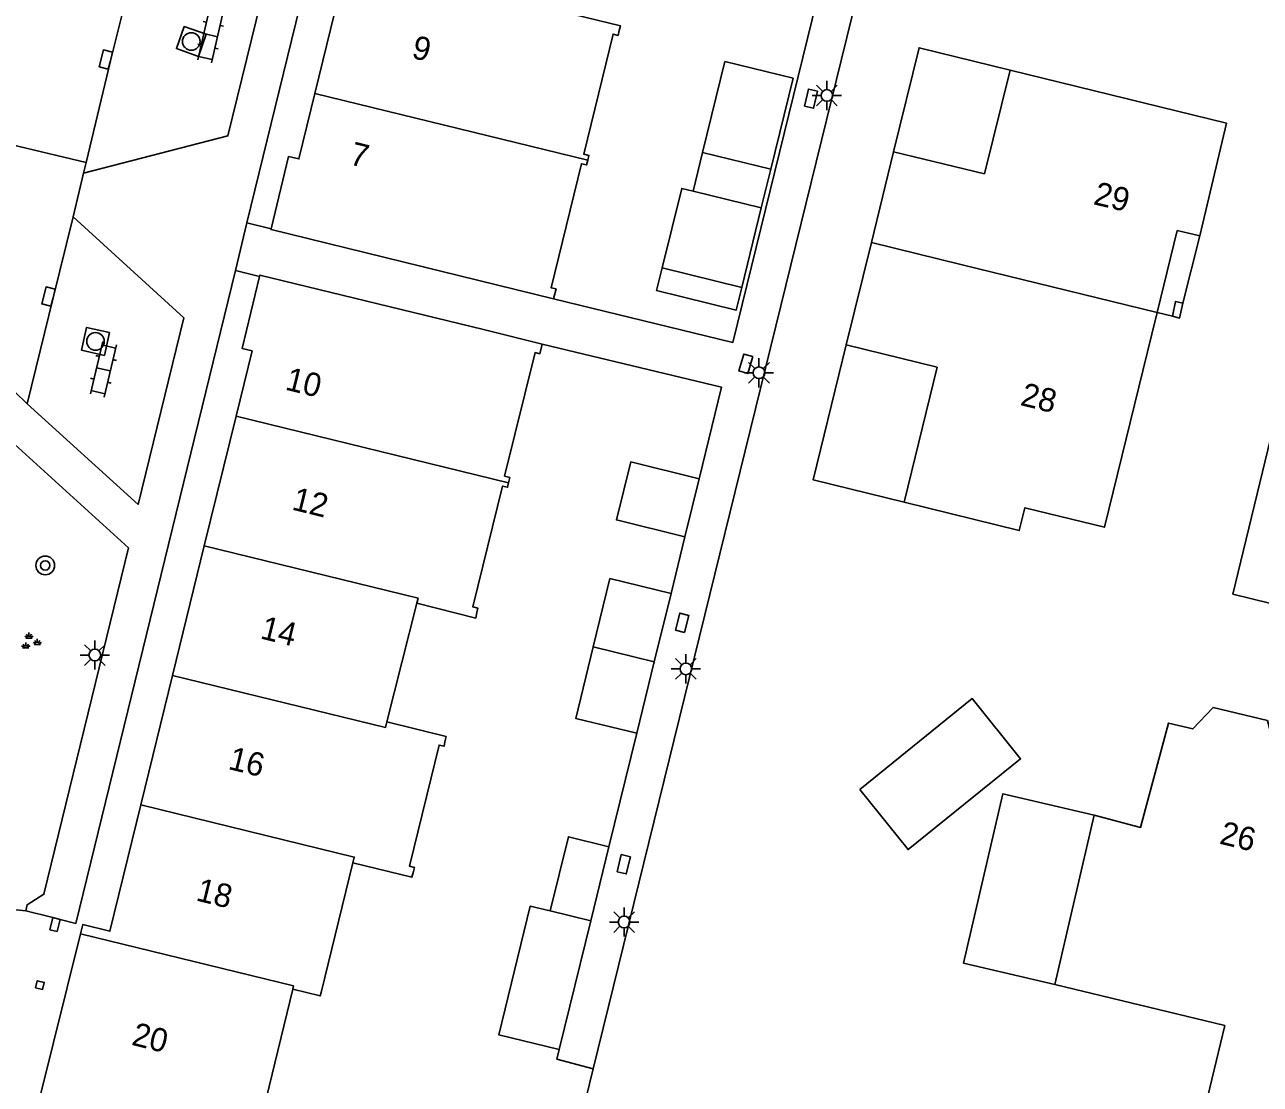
# Model space of a CAD drawing. Extents: x 125000 to 129004, y 397500 to 399008.
# Drawn here: x 126559.6 to 126612.3, y 398186.4 to 398231.7 of the extents above; entities that cross this region are included whole.
import ezdxf

# ---------------------------------------------------------------- set-up
doc = ezdxf.new("R2010")
doc.units = 0
for name, color, linetype in [('gg-afsc-hekwerk', 7, 'Continuous'), ('gg-afsc-muur', 7, 'Continuous'), ('gg-anno-huisnummerreeks BGT', 7, 'Continuous'), ('gg-bbg-bijgebouw', 7, 'Continuous'), ('gg-bbg-gedigitaliseerde bebouwing', 7, 'Continuous'), ('gg-bbg-gedigitaliseerde bijgebouw', 7, 'Continuous'), ('gg-bbg-hoofdgebouw', 7, 'Continuous'), ('gg-bbg-luifel en loopbrug', 7, 'Continuous'), ('gg-bbg-onder overbouw', 7, 'Continuous'), ('gg-bbg-pand overbouw', 7, 'Continuous'), ('gg-bbg-pilaar onder overbouw', 7, 'Continuous'), ('gg-bbg-pilaar pand', 7, 'Continuous'), ('gg-bbg-tussenscheiding', 7, 'Continuous'), ('gg-knt-verharding', 7, 'Continuous'), ('gg-knt-verharding nz', 7, 'Continuous'), ('gt-grn-groengrens', 7, 'Continuous'), ('gt-grn-weggrens', 7, 'Continuous'), ('gt-symb-boom', 7, 'Continuous'), ('gt-symb-groenvak', 7, 'Continuous'), ('gt-symb-klinker verharding', 7, 'Continuous'), ('gt-symb-kolk', 7, 'Continuous'), ('gt-symb-kolk center center', 7, 'Continuous'), ('gt-symb-lichtmast', 7, 'Continuous'), ('gt-symb-rioolschacht', 7, 'Continuous')]:
    doc.layers.add(name, color=color, linetype=linetype)

# ---------------------------------------------------------------- blocks, each defined once
blk = doc.blocks.new('gt0-LMAST')
at = {"layer": 'gt-symb-lichtmast'}
for p, q in [((-0.005, 0.246), (-0.005, 0.621)), ((-0.182, 0.173), (-0.447, 0.438)), ((0.172, 0.173), (0.437, 0.438)), ((-0.255, -0.004), (-0.63, -0.004)), ((-0.182, -0.181), (-0.447, -0.446)), ((-0.005, -0.254), (-0.005, -0.629)), ((0.437, -0.446), (0.172, -0.181)), ((0.245, -0.004), (0.62, -0.004))]:
    blk.add_line(p, q, dxfattribs=at)
blk.add_circle((-0.005, -0.004), 0.25, dxfattribs=at)
blk = doc.blocks.new('gt0-KOLKCC')
at = {"layer": 'gt-symb-kolk center center'}
blk.add_lwpolyline([(-0.375, 0.2), (0.375, 0.2), (0.375, -0.2), (-0.375, -0.2)], close=True, dxfattribs=at)
blk = doc.blocks.new('gt0-KOLK')
at = {"layer": 'gt-symb-kolk'}
blk.add_lwpolyline([(0, 0), (0.375, 0), (0.375, 0.4), (-0.375, 0.4), (-0.375, 0), (0, 0)], dxfattribs=at)
blk = doc.blocks.new('gt0-RS')
at = {"layer": 'gt-symb-rioolschacht'}
blk.add_lwpolyline([(-0.5, -0.5), (0.5, -0.5), (0.5, 0.5), (-0.5, 0.5)], close=True, dxfattribs=at)
blk.add_circle((0, 0), 0.375, dxfattribs=at)
blk = doc.blocks.new('gt0-KL1')
at = {"layer": 'gt-symb-klinker verharding'}
for p, q in [((-1.15, 0.3), (1.15, 0.3)), ((-1, -0.3), (-1, 0.3)), ((-0.5, 0.3), (-0.5, 0.45)), ((0, -0.3), (0, 0.3)), ((0.5, 0.3), (0.5, 0.45)), ((1, -0.3), (1, 0.3)), ((-1.15, -0.3), (1.15, -0.3)), ((-0.5, -0.45), (-0.5, -0.3)), ((0.5, -0.45), (0.5, -0.3))]:
    blk.add_line(p, q, dxfattribs=at)
blk = doc.blocks.new('gt0-GRVAK')
at = {"layer": 'gt-symb-groenvak'}
for p, q in [((-0.11, 0.189), (-0.228, 0.24)), ((-0.182, 0.153), (0.088, 0.153)), ((-0.091, 0.211), (-0.156, 0.322)), ((-0.047, 0.214), (-0.047, 0.393)), ((-0.004, 0.211), (0.061, 0.322)), ((0.015, 0.189), (0.133, 0.24)), ((0.262, -0.052), (0.197, 0.059)), ((0.305, -0.049), (0.305, 0.13)), ((0.349, -0.052), (0.414, 0.059)), ((-0.245, -0.228), (-0.363, -0.177)), ((-0.318, -0.264), (-0.047, -0.264)), ((-0.226, -0.206), (-0.291, -0.095)), ((-0.183, -0.203), (-0.183, -0.024)), ((-0.139, -0.206), (-0.074, -0.095)), ((-0.12, -0.228), (-0.002, -0.177)), ((0.243, -0.074), (0.125, -0.023)), ((0.17, -0.11), (0.441, -0.11)), ((0.368, -0.074), (0.486, -0.023))]:
    blk.add_line(p, q, dxfattribs=at)
blk = doc.blocks.new('gt0-BOOM')
at = {"layer": 'gt-symb-boom'}
for radius in [0.4, 0.2]:
    blk.add_circle((0, 0), radius, dxfattribs=at)

msp = doc.modelspace()

# ---------------------------------------------------------------- linework, layer by layer
at = {"layer": 'gg-afsc-hekwerk'}
for p, q in [((126598.275, 398245.797), (126583.84, 398187.058)), ((126583.84, 398187.058), (126583.293, 398184.831))]:
    msp.add_line(p, q, dxfattribs=at)
at = {"layer": 'gg-afsc-muur'}
msp.add_line((126561.064, 398193.438), (126560.753, 398193.513), dxfattribs=at)
for points in [[(126560.753, 398193.513), (126560.628, 398192.998), (126560.939, 398192.923), (126561.064, 398193.438)], [(126560.016, 398190.519), (126560.092, 398190.819), (126560.393, 398190.743), (126560.317, 398190.443), (126560.016, 398190.519)]]:
    msp.add_lwpolyline(points, dxfattribs=at)
at = {"layer": 'gg-bbg-bijgebouw'}
msp.add_lwpolyline([(126595.222, 398198.988), (126597.29, 398196.422), (126602.095, 398200.294), (126600.027, 398202.873), (126595.222, 398198.988)], dxfattribs=at)
at = {"layer": 'gg-bbg-gedigitaliseerde bebouwing'}
for p, q in [((126600.557, 398225.292), (126601.645, 398229.732)), ((126595.719, 398222.358), (126596.671, 398226.244)), ((126596.671, 398226.244), (126600.557, 398225.292)), ((126595.719, 398222.358), (126594.649, 398217.988)), ((126594.649, 398217.988), (126598.533, 398217.036)), ((126597.119, 398211.265), (126598.533, 398217.036))]:
    msp.add_line(p, q, dxfattribs=at)
at = {"layer": 'gg-bbg-gedigitaliseerde bijgebouw'}
for p, q in [((126588.509, 398226.212), (126591.423, 398225.497)), ((126591.017, 398223.843), (126588.103, 398224.558)), ((126590.182, 398220.444), (126591.017, 398223.843)), ((126586.783, 398221.278), (126590.182, 398220.444)), ((126587.755, 398209.787), (126588.364, 398212.265)), ((126586.447, 398204.447), (126587.161, 398207.361)), ((126586.447, 398204.447), (126585.698, 398201.389)), ((126584.511, 398196.545), (126583.735, 398193.375)), ((126583.735, 398193.375), (126582.388, 398187.876))]:
    msp.add_line(p, q, dxfattribs=at)
for points in [[(126591.423, 398225.497), (126592.376, 398229.382), (126589.463, 398230.097), (126588.509, 398226.212)], [(126588.103, 398224.558), (126587.617, 398224.677), (126586.783, 398221.278)], [(126588.364, 398212.265), (126585.44, 398212.984), (126584.831, 398210.506), (126587.755, 398209.787)], [(126583.839, 398205.086), (126584.553, 398208), (126587.161, 398207.361)], [(126583.839, 398205.086), (126583.09, 398202.028), (126585.698, 398201.389)], [(126582, 398193.8), (126582.776, 398196.97), (126584.511, 398196.545)], [(126582.388, 398187.876), (126579.804, 398188.509), (126581.151, 398194.008), (126582, 398193.8)]]:
    msp.add_lwpolyline(points, dxfattribs=at)
at = {"layer": 'gg-bbg-hoofdgebouw'}
for p, q in [((126573.3, 398234.265), (126571.947, 398228.728)), ((126607.927, 398219.367), (126607.7, 398218.441)), ((126579.145, 398218.641), (126581.662, 398218.02)), ((126567.225, 398209.404), (126568.582, 398214.94)), ((126565.868, 398203.867), (126567.225, 398209.404)), ((126576.298, 398206.949), (126575.028, 398201.884)), ((126564.512, 398198.331), (126565.868, 398203.867)), ((126603.557, 398190.659), (126605.23, 398197.897)), ((126572.211, 398190.312), (126573.575, 398195.858))]:
    msp.add_line(p, q, dxfattribs=at)
for points in [[(126582.479, 398232.241), (126585.005, 398231.622), (126584.951, 398231.419)], [(126583.602, 398225.881), (126583.657, 398226.085), (126583.443, 398226.137), (126584.684, 398231.269), (126584.898, 398231.217), (126584.951, 398231.419)], [(126601.645, 398229.732), (126610.887, 398227.468), (126609.751, 398222.645)], [(126571.947, 398228.728), (126571.264, 398225.933), (126570.827, 398226.038), (126570.085, 398222.948)], [(126582.147, 398219.962), (126582.253, 398220.378), (126582.039, 398220.43), (126583.333, 398225.728), (126583.547, 398225.676), (126583.602, 398225.881)], [(126582.147, 398219.962), (126570.077, 398222.917), (126570.085, 398222.948)], [(126568.582, 398214.94), (126569.267, 398217.733), (126568.84, 398217.837), (126569.588, 398220.912)], [(126579.145, 398218.641), (126569.602, 398220.97), (126569.588, 398220.912)], [(126607.7, 398218.441), (126605.676, 398210.198), (126602.275, 398211.028), (126602.037, 398210.056), (126597.119, 398211.265)], [(126581.662, 398218.02), (126581.561, 398217.612), (126581.357, 398217.662), (126580.05, 398212.377)], [(126580.222, 398212.092), (126580.182, 398211.904), (126579.968, 398211.957), (126578.697, 398206.789), (126578.911, 398206.736), (126578.872, 398206.555)], [(126580.05, 398212.377), (126580.272, 398212.323), (126580.222, 398212.092)], [(126578.872, 398206.555), (126578.821, 398206.316), (126576.298, 398206.949)], [(126605.23, 398197.897), (126607.219, 398197.367), (126608.409, 398201.83), (126609.449, 398201.578), (126610.316, 398202.497), (126612.633, 398201.933), (126612.964, 398200.69), (126616.313, 398199.914), (126615.266, 398195.608), (126616.15, 398195.392), (126615.507, 398192.755), (126618.35, 398192.045), (126616.459, 398184.298), (126610.07, 398185.832), (126610.817, 398188.898), (126603.557, 398190.659)], [(126575.028, 398201.884), (126577.551, 398201.251), (126577.503, 398201.021)], [(126577.503, 398201.021), (126577.465, 398200.836), (126577.251, 398200.888), (126575.988, 398195.713), (126576.202, 398195.661), (126576.155, 398195.483)], [(126561.937, 398192.825), (126562.033, 398193.213), (126563.188, 398192.929), (126564.512, 398198.331)], [(126573.575, 398195.858), (126576.092, 398195.247), (126576.155, 398195.483)], [(126571.01, 398190.463), (126569.36, 398183.659), (126560.213, 398185.888), (126561.937, 398192.825)], [(126572.211, 398190.312), (126572.175, 398190.166), (126571.01, 398190.463)]]:
    msp.add_lwpolyline(points, dxfattribs=at)
at = {"layer": 'gg-bbg-luifel en loopbrug'}
for p, q in [((126588.509, 398226.212), (126588.103, 398224.558)), ((126591.423, 398225.497), (126591.017, 398223.843))]:
    msp.add_line(p, q, dxfattribs=at)
for points in [[(126596.671, 398226.244), (126597.759, 398230.684), (126601.645, 398229.732)], [(126586.783, 398221.278), (126586.545, 398220.307), (126589.944, 398219.472), (126590.182, 398220.444)], [(126594.649, 398217.988), (126593.235, 398212.216), (126597.119, 398211.265)], [(126605.23, 398197.897), (126601.333, 398198.798), (126599.66, 398191.56), (126603.557, 398190.659)]]:
    msp.add_lwpolyline(points, dxfattribs=at)
at = {"layer": 'gg-bbg-onder overbouw'}
msp.add_lwpolyline([(126609.751, 398222.645), (126608.787, 398222.872), (126607.927, 398219.367)], dxfattribs=at)
at = {"layer": 'gg-bbg-pand overbouw'}
for p, q in [((126609.02, 398219.774), (126609.751, 398222.645)), ((126608.578, 398219.211), (126607.927, 398219.367))]:
    msp.add_line(p, q, dxfattribs=at)
at = {"layer": 'gg-bbg-pilaar onder overbouw'}
msp.add_lwpolyline([(126608.578, 398219.211), (126608.707, 398219.84), (126609.02, 398219.774)], dxfattribs=at)
at = {"layer": 'gg-bbg-pilaar pand'}
msp.add_lwpolyline([(126609.02, 398219.774), (126608.886, 398219.137), (126608.578, 398219.211)], dxfattribs=at)
at = {"layer": 'gg-bbg-tussenscheiding'}
for p, q in [((126571.947, 398228.728), (126583.602, 398225.881)), ((126599.604, 398221.407), (126595.719, 398222.358)), ((126607.927, 398219.367), (126599.604, 398221.407)), ((126568.582, 398214.94), (126580.222, 398212.092)), ((126586.447, 398204.447), (126583.839, 398205.086)), ((126582, 398193.8), (126583.735, 398193.375))]:
    msp.add_line(p, q, dxfattribs=at)
for points in [[(126567.225, 398209.404), (126576.354, 398207.171), (126576.298, 398206.949)], [(126565.868, 398203.867), (126574.967, 398201.641), (126575.028, 398201.884)], [(126564.512, 398198.331), (126573.634, 398196.1), (126573.575, 398195.858)], [(126561.937, 398192.825), (126571.043, 398190.598), (126571.01, 398190.463)]]:
    msp.add_lwpolyline(points, dxfattribs=at)
at = {"layer": 'gg-knt-verharding'}
for p, q in [((126561.625, 398223.455), (126562.069, 398225.332)), ((126570.085, 398222.948), (126569.038, 398223.206)), ((126569.588, 398220.912), (126568.565, 398221.17)), ((126559.665, 398215.469), (126559.136, 398215.983)), ((126587.161, 398207.361), (126587.755, 398209.787)), ((126584.511, 398196.545), (126585.698, 398201.389)), ((126560.753, 398193.513), (126559.6, 398193.803))]:
    msp.add_line(p, q, dxfattribs=at)
for points in [[(126569.038, 398223.206), (126577.216, 398256.596), (126576.568, 398256.765)], [(126562.069, 398225.332), (126568.237, 398226.919), (126570.853, 398237.604), (126564.673, 398235.951)], [(126582.147, 398219.962), (126589.798, 398218.091), (126593.384, 398232.701)], [(126637.288, 398207.087), (126635.858, 398201.273), (126611.159, 398207.336), (126616.438, 398229.133), (126641.153, 398223.117), (126639.719, 398217.178)], [(126561.625, 398223.455), (126566.347, 398219.147), (126564.4, 398211.171), (126559.665, 398215.469)], [(126568.565, 398221.17), (126561.732, 398193.264), (126561.064, 398193.438)], [(126588.364, 398212.265), (126589.322, 398216.175), (126581.662, 398218.02)], [(126559.6, 398193.803), (126559.659, 398194.06), (126560.377, 398194.51), (126563.993, 398209.313), (126558.823, 398214.01)], [(126583.84, 398187.058), (126582.288, 398187.467), (126582.388, 398187.876)]]:
    msp.add_lwpolyline(points, dxfattribs=at)
at = {"layer": 'gg-knt-verharding nz'}
msp.add_line((126562.176, 398225.781), (126562.069, 398225.332), dxfattribs=at)
for points in [[(126564.673, 398235.951), (126563.217, 398230.132), (126562.176, 398225.781)], [(126561.625, 398223.455), (126560.764, 398220.006), (126559.665, 398215.469)]]:
    msp.add_lwpolyline(points, dxfattribs=at)
at = {"layer": 'gt-grn-groengrens'}
msp.add_line((126559.6, 398193.803), (126559.178, 398193.847), dxfattribs=at)
at = {"layer": 'gt-grn-weggrens'}
for p, q in [((126562.176, 398225.781), (126551.902, 398228.239)), ((126569.038, 398223.206), (126568.565, 398221.17))]:
    msp.add_line(p, q, dxfattribs=at)

# ---------------------------------------------------------------- block references
at = {"layer": 'gt-symb-boom'}
msp.add_blockref('gt0-BOOM', (126560.432, 398208.565), dxfattribs=at)
at = {"layer": 'gt-symb-groenvak'}
msp.add_blockref('gt0-GRVAK', (126559.784, 398205.3), dxfattribs=at)
at = {"layer": 'gt-symb-klinker verharding'}
for p, rotation in [((126567.497, 398231.225), 76.82507339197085), ((126562.918, 398216.944), 76.82507339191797)]:
    msp.add_blockref('gt0-KL1', p, dxfattribs=dict(at, rotation=rotation))
at = {"layer": 'gt-symb-kolk'}
for p, rotation in [((126563.217, 398230.132), 75.93596328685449), ((126560.764, 398220.006), 75.99155651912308)]:
    msp.add_blockref('gt0-KOLK', p, dxfattribs=dict(at, rotation=rotation))
at = {"layer": 'gt-symb-kolk center center'}
for p, rotation in [((126593.141, 398228.508), 77.06118937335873), ((126590.357, 398217.182), -105.7172524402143), ((126587.635, 398206.112), 75.64421500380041), ((126585.143, 398195.792), 76.11658196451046)]:
    msp.add_blockref('gt0-KOLKCC', p, dxfattribs=dict(at, rotation=rotation))
at = {"layer": 'gt-symb-lichtmast'}
for p in [(126593.824, 398228.651), (126590.924, 398216.801), (126562.555, 398204.739), (126587.802, 398204.147), (126585.161, 398193.329)]:
    msp.add_blockref('gt0-LMAST', p, dxfattribs=at)
at = {"layer": 'gt-symb-rioolschacht'}
for p, rotation in [((126566.669, 398230.956), -109.14137379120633), ((126562.577, 398218.137), 167.58922528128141)]:
    msp.add_blockref('gt0-RS', p, dxfattribs=dict(at, rotation=rotation))

# ---------------------------------------------------------------- texts
at = {"layer": 'gg-anno-huisnummerreeks BGT'}
for s, rotation, p in [('9', 346.3, (126576.039, 398230.26)), ('7', 346.2, (126573.384, 398225.711)), ('29', 346.8, (126605.164, 398224.004)), ('10', 346.3, (126570.64, 398216.084)), ('28', 346.2, (126602.04, 398215.423)), ('12', 346.2, (126570.924, 398210.957)), ('14', 346.2, (126569.574, 398205.451)), ('16', 346.2, (126568.207, 398199.87)), ('26', 346.4, (126610.546, 398196.682)), ('18', 346.2, (126566.831, 398194.253)), ('20', 346, (126564.079, 398188.084))]:
    msp.add_text(s, height=1, rotation=rotation, dxfattribs=at).set_placement(p)

doc.saveas('drawing.dxf')
